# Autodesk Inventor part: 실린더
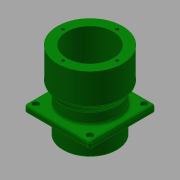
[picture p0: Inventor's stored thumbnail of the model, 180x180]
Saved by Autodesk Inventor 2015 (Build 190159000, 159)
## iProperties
Created: 2016-11
Part Number: 실린더
Material: 알루미늄 6061
Document SubType Name: Modeling
Designer: mduedu
Density: 2.71 g/cm^3
Mass: 551.099 g
Surface Area: 551.337 cm^2
Volume: 203.358 cm^3
Appearance: 진녹색
Author: mduedu
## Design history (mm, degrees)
sketch "스케치1"
  geometry: L1 (0, 0)-(0, 101); L2 (30, 0)-(30, 101); L3 (30, 101)-(42, 101); L4 (42, 101)-(42, 61); L5 (42, 61)-(35, 51); L6 (35, 51)-(35, 0); L7 (35, 0)-(30, 0)
  constraints: 14 end point, 4 parallel, 2 horizontal alignment, 1 perpendicular, 1 vertical
  dimensions: "d0" = 101 distance of L1.start L1.end; "d1" = 60 diameter of L2.end L1; "d2" = 84 diameter of L3.end L1; "d3" = 70 diameter of L6.end L1; "d4" = 40 distance of L3.end L4.end; "d5" = 50 vertical distance of L5.end L3.end
revolve "회전1" sketch "스케치1" stored, may be unused: angle "d6" = 90 deg
node "작업 평면1"
sketch "스케치2"
  geometry: L1 (-42.5, -42.5)-(42.5, -42.5); L2 (42.5, -42.5)-(42.5, 42.5); L3 (42.5, 42.5)-(-42.5, 42.5); L4 (-42.5, 42.5)-(-42.5, -42.5); L5 (-42.5, -42.5)-(42.5, 42.5); L6 (42.5, -42.5)-(-42.5, 42.5); C1 r 35 at (0, 0) reference; C2 r 35 at (0, 0); 1 further point
  constraints: 12 end point, 2 midpoint, 2 parallel, 2 perpendicular, 1 centre point, 1 coincident, 1 concentric, 1 horizontal
  dimensions: "d8" = 85 distance of L2.end L3.end
extrude "돌출1" join sketch "스케치2" distance "d10" = 8; taper "d11" = 0 deg
fillet "모깎기1" dims "d12" = 3
fillet "모깎기2" dims "d13" = 3
chamfer "모따기1" distance "d14" = 1; stored, may be unused: second distance "d15" = 2, angle "d16" = 45 deg
chamfer "모따기2" distance "d17" = 5; stored, may be unused: second distance "d18" = 2, angle "d19" = 15 deg
sketch "스케치3"
  geometry: L1 (-35, -35)-(35, -35); L2 (35, -35)-(35, 35); L3 (35, 35)-(-35, 35); L4 (-35, 35)-(-35, -35); L5 (-35, -35)-(35, 35); L6 (35, -35)-(-35, 35); 5 further points
  constraints: 12 end point, 4 coincident, 2 midpoint, 2 parallel, 1 horizontal, 1 perpendicular
  dimensions: "d20" = 70 distance of L3.end L2.end; "d21" = 70 distance of L2.end L1.end
sketch "스케치4"
  geometry: 4 further points
  constraints: 4 other
hole "구멍1" sketch "스케치4" at (-35, 35), (35, 35), (35, -35), (-35, -35) diameter "d22" = 4.5; stored, may be unused: countersink angle "d26" = 90 deg, drill point angle "d28" = 0 deg; dims "d23" = 6, "d24" = 8, "d25" = 4.6, "d27" = 8
sketch "스케치5"
  geometry: 4 further points
  constraints: 4 other
hole "구멍2" sketch "스케치5" at (0, -35), (35, 0), (-35, 0), (0, 35) diameter "d29" = 4.134; stored, may be unused: countersink angle "d33" = 90 deg, drill point angle "d35" = 120 deg; dims "d30" = 7.5, "d31" = 4, "d32" = 2, "d34" = 10
node "솔리드1"
other parameters: "d7" = -27
